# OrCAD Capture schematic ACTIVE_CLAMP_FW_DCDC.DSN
size A
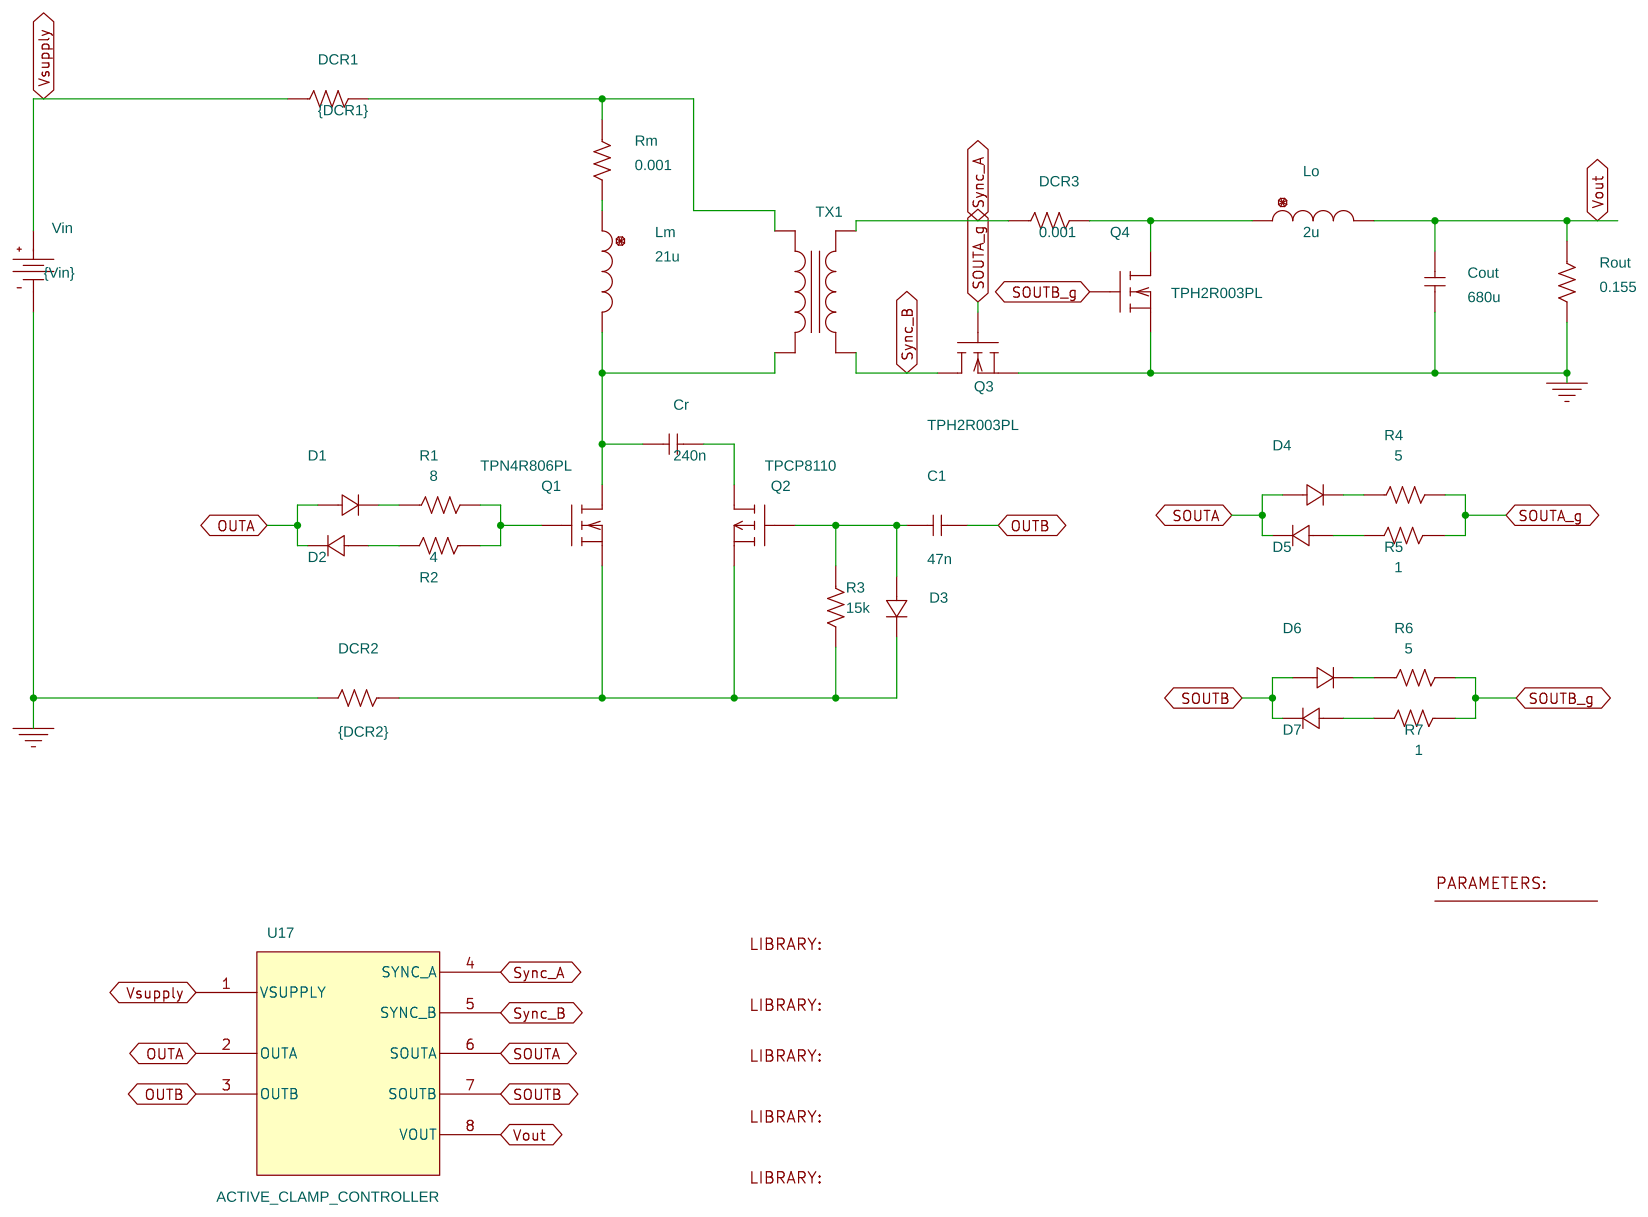
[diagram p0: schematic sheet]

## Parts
1  PARAM
C1  47n  [cap196]
Cout  680u  [cap196]
Cr  240n  [cap196]
D1  Diode_nom
D2  Diode_nom
D3  Diode_nom
D4  Diode_nom
D5  Diode_nom
D6  Diode_nom
D7  Diode_nom
DCR1  {DCR1}  [AXRC05]
DCR2  {DCR2}  [AXRC05]
DCR3  0.001  [AXRC05]
LIB2  LIB
LIB3  LIB
LIB5  LIB
LIB6  LIB
LIB7  LIB
Lm  21u  [DISC350x175LS200x100034]
Lo  2u  [DISC350x175LS200x100034]
Q1  TPN4R806PL
Q2  TPCP8110
Q3  TPH2R003PL
Q4  TPH2R003PL
R1  8  [AXRC05]
R2  4  [AXRC05]
R3  15k  [AXRC05]
R4  5  [AXRC05]
R5  1  [AXRC05]
R6  5  [AXRC05]
R7  1  [AXRC05]
Rm  0.001  [AXRC05]
Rout  0.155  [AXRC05]
TX1  XFRM_NONLINEAR
U17  ACTIVE_CLAMP_CONTROLLER
Vin  VDC

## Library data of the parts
1 = PARAM: DCR1: 5m; DCR2: 5m; Fc: 150k; Td: 370n; Vdrv_H_p: 12; Vdrv_H_r: 12; Vdrv_H_s: 5; Vin: 24; Vout: 3.3
C1 Cout Cr = C
D1-D7 = Diode_nom
DCR1-DCR3 R1-R7 Rm Rout = R
LIB2 = LIB: FILENAME: ../../../lib/TPH2R003PL_PSpice_20180808.lib
LIB3 = LIB: FILENAME: ../../../lib/diode_nom.lib
LIB5 = LIB: FILENAME: ../../../lib/TPN4R806PL_PSpice_20161118.lib
LIB6 = LIB: FILENAME: ../../../lib/TPCP8110_PSpice_20150529.lib
LIB7 = LIB: FILENAME: ../../../lib/Active_Clamp_Controller.lib
Lm Lo = L
Q1 = TPN4R806PL
Q2 = TPCP8110
Q3 Q4 = TPH2R003PL
TX1 = XFRM_NONLINEAR: COUPLING: 1; L1_TURNS: 20; L2_TURNS: 10
U17 = ACTIVE_CLAMP_CONTROLLER
Vin = VDC: DC: {Vin}

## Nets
0: Cout.2 DCR2.2 Q3.0(s) Q4.0(s) Rout.2 Vin.1(-)
OUTA: D1.0(1) D2.1(2) U17.2(OUTA)
OUTB: C1.2 U17.3(OUTB)
SOUTA: D4.0(1) D5.1(2) U17.6(SOUTA)
SOUTA_g: Q3.1(g) R4.2 R5.1
SOUTB: D6.0(1) D7.1(2) U17.7(SOUTB)
SOUTB_g: Q4.1(g) R6.2 R7.1
Sync_A: DCR3.1 TX1.2(3) U17.4(SYNC_A)
Sync_B: Q3.2(d) TX1.3(4) U17.5(SYNC_B)
Vout: Cout.1 Lo.2 Rout.1 U17.8(VOUT)
Vsupply: DCR1.1 U17.1(VSUPPLY) Vin.0(+)
N16198367: DCR1.2 Rm.1 TX1.0(1)
N16198415: Lm.1 Rm.2
N16198551: DCR3.2 Lo.1 Q4.2(d)
N16198661: Cr.1 Lm.2 Q1.2(d) TX1.1(2)
N16198771: Cr.2 Q2.2(d)
N16198879: D4.1(2) R4.1
N16198909: D1.1(2) R1.1
N16198913: Q1.1(g) R1.2 R2.1
N16199071: C1.1 D3.0(1) Q2.1(g) R3.1
N16199111: D5.0(1) R5.2
N16199139: D2.0(1) R2.2
N16199151: D3.1(2) DCR2.1 Q1.0(s) Q2.0(s) R3.2
N16199261: D6.1(2) R6.1
N16199375: D7.0(1) R7.2
